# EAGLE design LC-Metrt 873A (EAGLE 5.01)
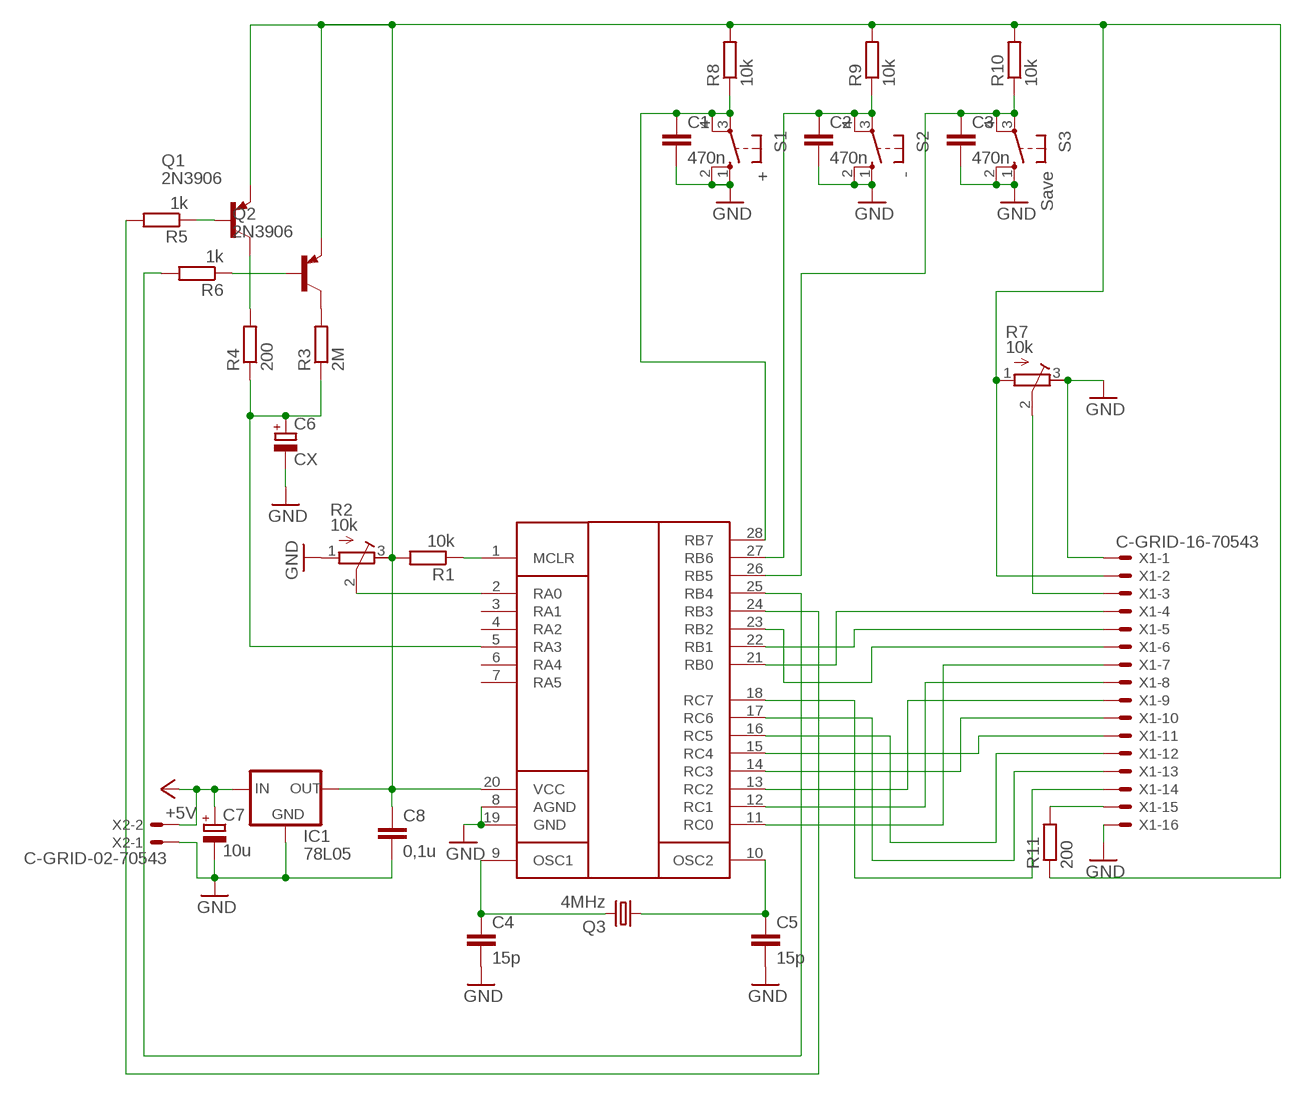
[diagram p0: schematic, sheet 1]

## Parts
C1  470n  C-EU050-025X075  [C050-025X075]
C2  470n  C-EU050-025X075  [C050-025X075]
C3  470n  C-EU050-025X075  [C050-025X075]
C4  15p  C-EU050-025X075  [C050-025X075]
C5  15p  C-EU050-025X075  [C050-025X075]
C6  CX  CPOL-EUE5-8.5  [E5-8,5]
C7  10u  CPOL-EUSANYO_A'  [SANYO-OSCON_A']
C8  0,1u  C-EU050-025X075  [C050-025X075]
IC1  78L05  78XXL  [78XXL]
Q1  2N3906  [TO92]
Q2  2N3906  [TO92]
Q3  4MHz  CRYSTALHC49S  [HC49/S]
R1  10k  R-EU_0207/7  [0207/7]
R2  10k  R-TRIMM3339P  [RTRIM3339P]
R3  2M  R-EU_0207/7  [0207/7]
R4  200  R-EU_0207/7  [0207/7]
R5  1k  R-EU_0207/7  [0207/7]
R6  1k  R-EU_0207/7  [0207/7]
R7  10k  R-TRIMM3339P  [RTRIM3339P]
R8  10k  R-EU_0207/7  [0207/7]
R9  10k  R-EU_0207/7  [0207/7]
R10  10k  R-EU_0207/7  [0207/7]
R11  200  R-EU_0207/7  [0207/7]
S1  +  10-XX  [B3F-10XX]
S2  -  10-XX  [B3F-10XX]
S3  Save  10-XX  [B3F-10XX]
U$1  PIC16F873A  [SO-28W]
X1  C-GRID-16-70543  [70543-16]
X2  C-GRID-02-70543  [70543-02]

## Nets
+5V: C7.+ IC1.IN X2.2
GND: C1.2 C2.2 C3.2 C4.2 C5.2 C6.- C7.- C8.2 IC1.GND R2.1(E) R7.3(A) S1.1(S) S1.2(S1) S2.1(S) S2.2(S1) S3.1(S) S3.2(S1) U$1.8(AGND) U$1.19(GND) X1.1 X1.16 X2.1
N$1: Q1.2(B) R5.1
N$2: Q1.1(C) R4.2
N$3: Q2.1(C) R3.2
N$4: Q2.2(B) R6.1
N$5: R2.2(S) U$1.2(RA0)
N$6: C5.1 Q3.1 U$1.10(OSC2)
N$7: R1.1 U$1.1(MCLR)
N$8: C6.+ R3.1 R4.1 U$1.5(RA3)
N$9: R5.2 U$1.24(RB3)
N$10: R6.2 U$1.25(RB4)
N$11: R7.2(S) X1.3
N$12: C1.1 R8.1 S1.3(P) S1.4(P1) U$1.28(RB7)
N$13: C2.1 R9.1 S2.3(P) S2.4(P1) U$1.27(RB6)
N$14: C3.1 R10.1 S3.3(P) S3.4(P1) U$1.26(RB5)
N$15: C4.1 Q3.2 U$1.9(OSC1)
N$16: U$1.21(RB0) X1.4
N$17: U$1.22(RB1) X1.5
N$18: U$1.23(RB2) X1.6
N$19: U$1.11(RC0) X1.7
N$20: U$1.12(RC1) X1.8
N$21: U$1.13(RC2) X1.9
N$22: U$1.14(RC3) X1.10
N$23: U$1.15(RC4) X1.11
N$24: U$1.16(RC5) X1.12
N$25: U$1.17(RC6) X1.13
N$26: U$1.18(RC7) X1.14
N$27: C8.1 IC1.OUT Q1.3(E) Q2.3(E) R1.2 R2.3(A) R7.1(E) R8.2 R9.2 R10.2 R11.1 U$1.20(VCC) X1.2
N$28: R11.2 X1.15
Unconnected: U$1.3(RA1) U$1.4(RA2) U$1.6(RA4) U$1.7(RA5)

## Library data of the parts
C1-C5 C8 = rcl:C-EU: CAPACITOR, European symbol
C6 C7 = rcl:CPOL-EU: POLARIZED CAPACITOR, European symbol
IC1 = v-reg:78XXL: VOLTAGE REGULATOR
Q1 Q2 = transistor-pnp:2N3906: PNP Transistor
Q3 = crystal:CRYSTAL: CRYSTAL
R1 R3-R6 R8-R11 = rcl:R-EU_: RESISTOR, European symbol
R2 R7 = rcl:R-TRIMM: Trimm resistor
S1-S3 = switch-omron:10-XX: OMRON SWITCH
U$1 = PIC16F873A:PIC16F873A
X1 = con-molex:C-GRID-16: CONNECTOR wire to board 2.54 mm (0.100") pitch header
X2 = con-molex:C-GRID-02: CONNECTOR

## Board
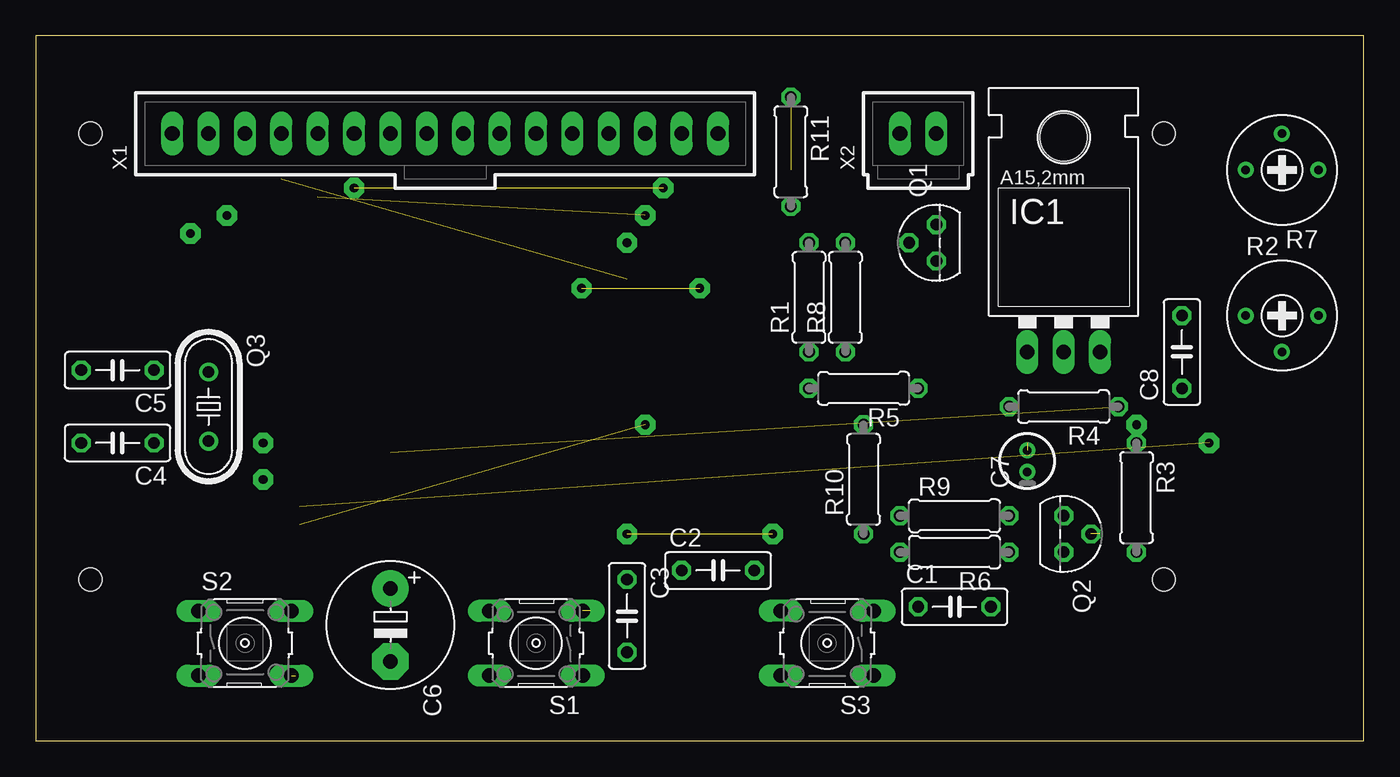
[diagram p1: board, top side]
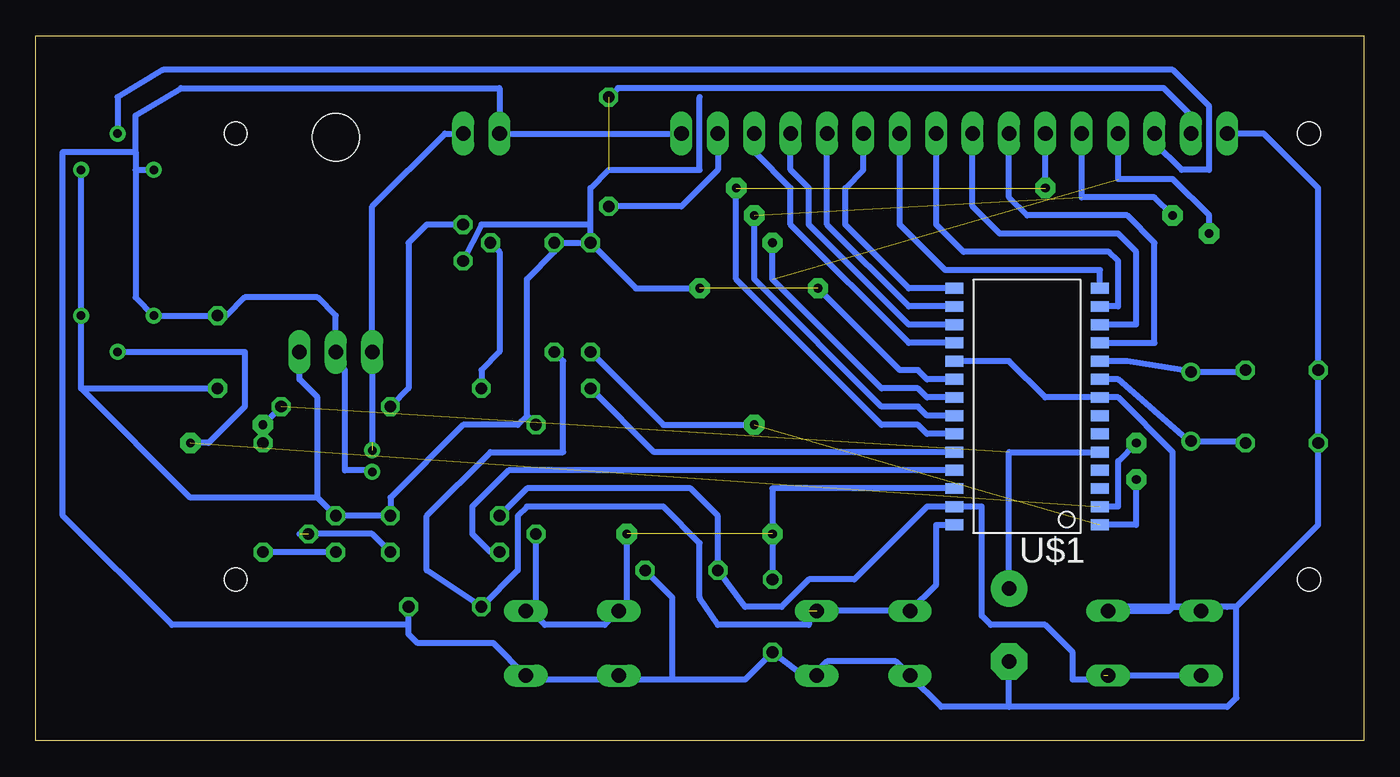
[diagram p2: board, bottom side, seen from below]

Size 92.69 x 49.2 mm. Coordinates in mm from the lower left corner, seen from the top.
Outline: 0,0 92.69,0 92.69,49.2 0,49.2 0,0
Copper layers (1*16): Top 0.035mm / dielectric 1.5mm / Bottom 0.035mm
Design rules "default": minimum track width 20mil, minimum drill 14mil, track to track 10mil, track to pad 10mil, pad to pad 10mil, via to via 10mil, smd to smd 8mil, copper to edge 40mil, drill to drill 8mil, minimum pad ring 10mil, minimum via ring 8mil, stop-mask expansion 4mil, vias tented up to drill 0mil, thermal gap 10mil
Holes 0.6 mm at -40.01,44.92
Holes 1.6 mm at 3.8,42.38 3.8,11.27 78.73,11.27 78.73,42.38

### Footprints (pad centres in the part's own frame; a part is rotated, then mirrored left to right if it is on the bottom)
C050-025X075 = drill 0.813 octagon: 1 -2.54,0; 2 2.54,0
E5-8,5 = drill 1.016 pad 2.54 round: + -2.54,0 | drill 1.016 pad 2.54 octagon: - 2.54,0
SANYO-OSCON_A' = drill 0.6 pad 1 round: + 0.75,0; - -0.75,0
78XXL = drill 1.016 long: GND 0,-3.81; IN -2.54,-3.81; OUT 2.54,-3.81 | hole 3.302: 0,11.176
TO92 = drill 0.813 octagon: 1 1.27,0; 2 0,1.905; 3 -1.27,0
HC49/S = drill 0.813 round: 1 -2.413,0; 2 2.413,0
0207/7 = drill 0.813 octagon: 1 -3.81,0; 2 3.81,0
RTRIM3339P = drill 0.61 round: 1 -2.54,0; 2 0,-2.54; 3 2.54,0
B3F-10XX = drill 1.016 long: 1 -3.251,2.261; 2 3.251,2.261; 3 -3.251,-2.261; 4 3.251,-2.261
SO-28W = smd 0.762 x 1.27: 1 -8.255,-5.08; 2 -6.985,-5.08; 3 -5.715,-5.08; 4 -4.445,-5.08; 5 -3.175,-5.08; 6 -1.905,-5.08; 7 -0.635,-5.08; 8 0.635,-5.08; 9 1.905,-5.08; 10 3.175,-5.08; 11 4.445,-5.08; 12 5.715,-5.08; 13 6.985,-5.08; 14 8.255,-5.08; 15 8.255,5.08; 16 6.985,5.08; 17 5.715,5.08; 18 4.445,5.08; 19 3.175,5.08; 20 1.905,5.08; 21 0.635,5.08; 22 -0.635,5.08; 23 -1.905,5.08; 24 -3.175,5.08; 25 -4.445,5.08; 26 -5.715,5.08; 27 -6.985,5.08; 28 -8.255,5.08
70543-16 = drill 1.016 long: 1 -19.05,0; 2 -16.51,0; 3 -13.97,0; 4 -11.43,0; 5 -8.89,0; 6 -6.35,0; 7 -3.81,0; 8 -1.27,0; 9 1.27,0; 10 3.81,0; 11 6.35,0; 12 8.89,0; 13 11.43,0; 14 13.97,0; 15 16.51,0; 16 19.05,0
70543-02 = drill 1.016 long: 1 -1.27,0; 2 1.27,0

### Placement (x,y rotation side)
C1  64.13,9.36 0 top
C2  47.62,11.9 0 top
C3  41.27,8.73 270 top
C4  5.71,20.79 180 top
C5  5.71,25.87 180 top
C6  24.76,8.09 270 top
C7  69.21,19.52 90 top
C8  80,27.14 90 top
IC1  71.75,30.95 0 top
Q1  62.86,34.76 90 top
Q2  71.75,14.44 270 top
Q3  12.06,23.33 270 top
R1  53.97,30.95 90 top
R2  86.99,29.68 0 top
R3  76.83,16.98 270 top
R4  71.75,23.33 180 top
R5  57.78,24.6 180 top
R6  64.13,13.17 180 top
R7  86.99,39.84 180 top
R8  56.51,30.95 90 top
R9  64.13,15.71 0 top
R10  57.78,18.25 90 top
R11  52.7,41.11 270 top
S1  34.92,6.82 180 top
S2  14.6,6.82 0 top
S3  55.24,6.82 180 top
U$1  23.49,23.33 90 bottom
X1  28.57,42.38 0 top
X2  61.59,42.38 0 top

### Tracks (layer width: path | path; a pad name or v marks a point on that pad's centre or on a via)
+5V  (1 unrouted)
  Bottom 0.406: X2.2 64.13,42.38 69.21,37.3 IC1.IN 69.21,20.79
GND
  Bottom 0.406: X1.1 6.98,42.38 3.17,38.57 C5.2 C4.2 3.17,15.07 8.89,9.36 | 13.33,9.36 13.61,9.08 S2.2 17.57,9.36 9.52,9.36 | 13.33,9.36 13.33,20.16 17.14,23.96 U$1.8 22.22,23.96 24.76,26.51 U$1.19 | X1.16 X2.1 60.32,45.55 82.55,45.55 85.72,43.65 85.72,41.11 | 85.72,41.11 85.72,39.84 | 85.72,39.84 85.72,30.95 R2.1 C8.2 79.37,29.68 78.1,30.95 73.02,30.95 71.75,29.68 IC1.GND 71.11,25.87 71.11,18.88 69.21,18.88 C7.- | 85.72,39.84 R7.3 | 13.33,9.36 11.43,9.36 11.43,9.16 S2.1 11.07,9.36 9.52,9.36 | 8.89,9.36 9.52,9.36 | 8.89,9.36 8.89,3.01 9.52,2.38 24.76,2.38 | 24.76,2.38 C6.- | 24.76,2.38 29.48,2.38 S1.2 32.66,5.55 37.46,5.55 38.1,4.91 | 38.1,4.91 38.1,4.64 S1.1 | 38.1,4.91 38.73,4.28 C3.2 43.18,4.28 48.26,4.28 | 52.07,4.48 52.07,4.28 48.26,4.28 | 52.07,4.48 S3.2 | 52.07,4.48 52.27,4.28 58.41,4.28 58.41,4.48 S3.1 60.75,6.82 66.03,6.82 66.67,7.46 66.67,8.09 | C2.2 48.26,10 48.26,4.28 | 66.67,8.09 C1.2 | 66.67,8.09 83.18,8.09 90.8,15.71 90.8,41.11 85.72,41.11
N$1
  Bottom 0.406: Q1.2 60.32,34.13 60.32,27.14 61.59,25.87 R5.1
N$2
  Bottom 0.406: Q1.1 65.4,36.03 66.67,34.76 66.67,24.6 R4.2
N$3
  Bottom 0.406: Q2.1 R3.2
N$4  (1 unrouted)
  Bottom 0.406: R6.1 69.21,14.44 74.29,14.44
N$5  (1 unrouted)
  Bottom 0.406: U$1.2 17.14,16.35 17.14,19.52 15.87,20.79 | R2.2 78.1,27.14 78.1,23.33 80.64,20.79 81.91,20.79
N$6
  Bottom 0.406: 11.93,25.74 16.5,26.51 U$1.10 | Q3.1 11.93,25.74 | 11.93,25.74 8.38,25.74 C5.1
N$7  (1 unrouted)
  Bottom 0.406: U$1.1 15.87,15.07 15.87,18.25 | R1.1 48.89,22.06 42.54,22.06
N$8  (via drill 0.6 pad 1.42)  (1 unrouted)
  Bottom 0.406: R4.1 v76.83,22.06 R3.1 | U$1.5 24.76,20.16 C6.+
N$9
  Bottom 0.406: U$1.24 49.53,20.16 R5.2
N$10
  Bottom 0.406: U$1.25 59.69,18.88 62.23,16.35 62.23,14.44 60.96,13.17 R6.2
N$11
  Bottom 0.406: X1.3 14.6,41.74 12.7,39.84 10.79,39.84 10.79,44.29 13.33,46.82 83.81,46.82 86.99,44.92 R7.2
N$12  (1 unrouted)
  Bottom 0.406: R8.1 55.88,26.51 55.88,20.16 60.96,20.16 65.4,15.71 65.4,11.9 C1.1 59.05,11.9 59.05,15.71 58.41,16.35 48.89,16.35 46.35,13.8 46.35,10 45.08,8.09 38.73,8.09 38.73,9.08 | U$1.28 29.84,15.07 29.84,10.91 S1.4 38.73,9.08 | 38.73,9.08 38.73,9.36
N$13  (1 unrouted)
  Bottom 0.406: S2.3 18.13,4.56 18.41,4.28 20.31,4.28 20.31,6.19 22.22,8.09 26.03,8.09 26.66,8.73 26.66,16.35 U$1.27 30.47,16.35 35.55,11.27 38.73,11.27 40.64,9.36 43.18,9.36 C2.1 45.08,15.71 46.98,17.62 58.41,17.62 R9.1
N$14  (1 unrouted)
  Bottom 0.406: 51.43,14.44 51.43,9.64 S3.4 52.98,8.09 57.15,8.09 58.41,9.36 58.41,9.16 S3.3 57.78,9.79 R10.1 | C3.1 41.27,14.44 41.27,17.62 U$1.26
N$15
  Bottom 0.406: U$1.9 17.14,25.24 12.06,20.79 Q3.2 8.38,20.92 C4.1
N$16  (via drill 0.6 pad 1.42)  (1 unrouted)
  Bottom 0.406: v41.27,34.76 41.27,32.22 33.65,24.6 31.11,24.6 30.47,23.96 U$1.21 | X1.4 17.14,39.21 13.33,39.21 10.79,36.66 10.79,35.4
N$17  (via drill 0.6 pad 1.42)  (1 unrouted)
  Bottom 0.406: X1.5 19.68,37.94 14.6,37.94 13.33,36.66 | U$1.22 30.47,22.7 31.11,23.33 33.65,23.33 42.54,32.22 v42.54,36.66
N$18  (via drill 0.6 pad 1.42)  (1 unrouted)
  Bottom 0.406: v22.22,38.57 X1.6 | U$1.23 30.47,21.43 31.11,22.06 33.65,22.06 43.81,32.22 v43.81,38.57
N$19
  Bottom 0.406: U$1.11 14.6,27.77 14.6,34.76 16.5,36.66 23.49,36.66 24.76,37.94 X1.7
N$20
  Bottom 0.406: X1.8 27.3,37.3 25.39,35.4 17.14,35.4 15.87,34.13 15.87,29.05 U$1.12
N$21
  Bottom 0.406: X1.9 29.84,36.03 27.93,34.13 17.77,34.13 17.14,33.49 17.14,30.32 U$1.13
N$22
  Bottom 0.406: X1.10 32.38,36.03 29.2,32.85 18.41,32.85 U$1.14
N$23
  Bottom 0.406: U$1.15 31.74,31.59 36.19,36.03 36.19,38.57 34.92,39.84 X1.11
N$24
  Bottom 0.406: U$1.16 31.74,30.32 37.46,36.03 X1.12
N$25
  Bottom 0.406: U$1.17 31.74,29.05 38.73,36.03 38.73,38.57 40,39.84 X1.13
N$26
  Bottom 0.406: U$1.18 31.74,27.77 40,36.03 40,38.57 42.54,41.11 X1.14
N$27  (2 unrouted)
  Bottom 0.406: X1.2 12.06,43.65 13.97,45.55 52.07,45.55 R11.1 | 53.97,36.03 61.59,36.03 Q1.3 | R1.2 53.97,36.03 | 53.97,36.03 53.97,38.57 52.7,39.84 46.35,39.84 46.35,44.92 | U$1.20 30.47,25.24 31.11,25.87 32.38,25.87 38.1,31.59 | R1.2 50.8,31.59 46.35,31.59 | R7.1 R2.3 89.53,24.6 | R1.2 R8.2 56.51,34.13 58.41,32.22 58.41,22.7 | 73.02,16.98 Q2.3 R9.2 67.94,16.98 62.86,22.06 59.05,22.06 58.41,22.7 | 73.02,16.98 73.02,23.96 74.29,25.24 IC1.OUT | 89.53,24.6 81.91,16.98 73.02,16.98 | 89.53,24.6 C8.1 | R10.2 58.41,22.7
N$28
  Bottom 0.406: X1.15 45.08,39.84 47.62,37.3 R11.2
N$29  (via drill 0.6 pad 1.42)
  other vias: 38.1,31.59
N$30  (via drill 0.6 pad 1.42)
  other vias: 46.35,31.59
N$31  (via drill 0.6 pad 1.42)
  other vias: 13.33,36.66
N$32  (via drill 0.6 pad 1.42)
  other vias: 10.79,35.4
N$33  (via drill 0.6 pad 1.42)
  other vias: 15.87,20.79
N$34  (via drill 0.6 pad 1.42)
  other vias: 15.87,18.25
N$35  (via drill 0.6 pad 1.42)
  other vias: 42.54,22.06
N$36  (via drill 0.6 pad 1.42)
  other vias: 81.91,20.79
N$37  (via drill 0.6 pad 1.42)
  other vias: 41.27,14.44
N$38  (via drill 0.6 pad 1.42)
  other vias: 51.43,14.44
